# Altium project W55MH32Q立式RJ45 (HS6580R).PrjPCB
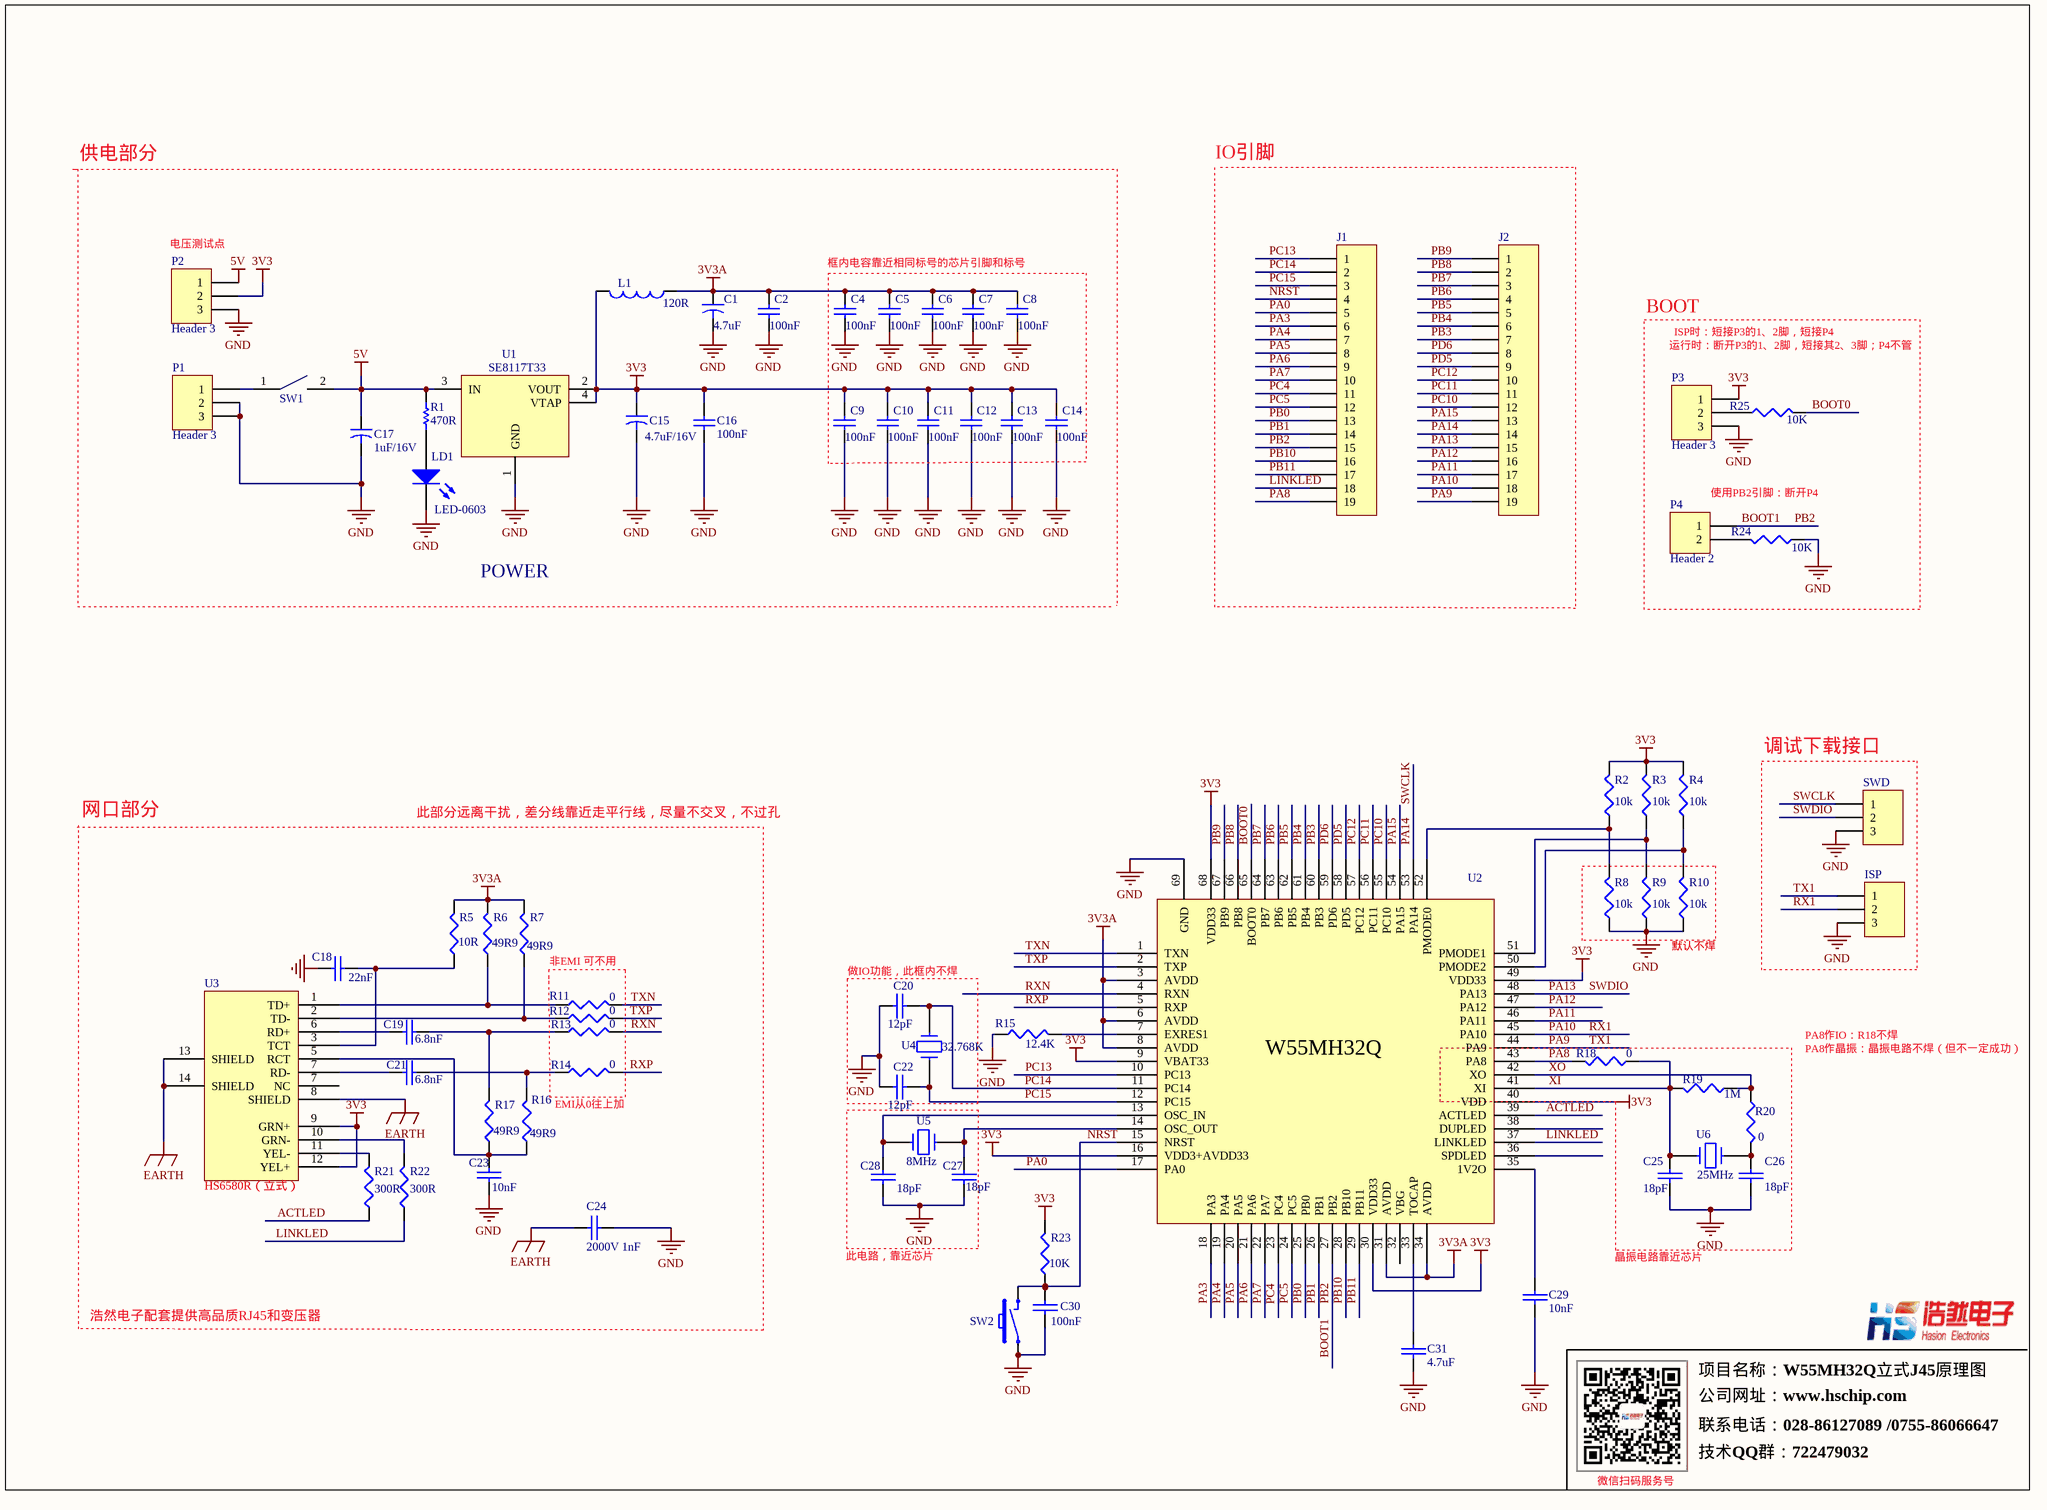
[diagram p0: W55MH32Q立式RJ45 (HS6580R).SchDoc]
1 sheet, 73 parts. Net scope: global (net labels, ports and power ports of the same name join across sheets).

## Sheet W55MH32Q立式RJ45 (HS6580R).SchDoc
size 381 x 279 mm; PageSetup: Record=PageOptions?CenterHorizontal=True?CenterVertical=True?PrintScale=0.74?XCorrection=1.00?YCorrection=1.00?PrintKind=0?BorderSize=5000000?LeftOffset=0?BottomOffset=0?Orientation=2?PaperLength=1000?PaperWidth=1000?Scale=100?PaperSource=7?PrintQuality=-4?MediaType=1?DitherType=10?PaperKind=A4?PrintScaleMode=1

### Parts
C1  4.7uF  [3216]
C2  100nF  [0402]
C4  100nF  [0402]
C5  100nF  [0402]
C6  100nF  [0402]
C7  100nF  [0402]
C8  100nF  [0402]
C9  100nF  [0402]
C10  100nF  [0402]
C11  100nF  [0402]
C12  100nF  [0402]
C13  100nF  [0402]
C14  100nF  [0402]
C15  4.7uF/16V  [3216]
C16  100nF  [0402]
C17  1uF/16V  [3216]
C18  22nF  [0402]
C19  6.8nF  [0402]
C20  12pF  [0402]
C21  6.8nF  [0402]
C22  12pF  [0402]
C23  10nF  [0402]
C24  2000V 1nF  [1808-C-SMD]
C25  18pF  [0402]
C26  18pF  [0402]
C27  18pF  [0402]
C28  18pF  [0402]
C29  10nF  [0402]
C30  100nF  [0402]
C31  4.7uF  [3216]
ISP  Header 3  [HDR1X3]  (value not drawn)
J1  Header 19  [SIP19]  (value not drawn)
J2  Header 19  [SIP19]  (value not drawn)
L1  120R  [0603]
LD1  LED-0603  [0603 - LED]
P1  Header 3  [PLUG]
P2  Header 3  [HDR1X3]
P3  Header 3  [HDR1X3]
P4  Header 2  [HDR1X2]
R1  470R  [0402]
R2  10k  [0402]
R3  10k  [0402]
R4  10k  [0402]
R5  10R  [0402]
R6  49R9  [0402]
R7  49R9  [0402]
R8  10k  [0402]
R9  10k  [0402]
R10  10k  [0402]
R11  0  [0402]
R12  0  [0402]
R13  0  [0402]
R14  0  [0402]
R15  12.4K  [0402]
R16  49R9  [0402]
R17  49R9  [0402]
R18  0  [0402]
R19  1M  [0402]
R20  0  [0402]
R21  300R  [0402]
R22  300R  [0402]
R23  10K  [0402]
R24  10K  [0402]
R25  10K  [0402]
SW1  SW  [SWITCH-3]  (value not drawn)
SW2  RSTn  [PB-4]  (value not drawn)
SWD  Header 3  [HDR1X3]  (value not drawn)
U1  SE8117T33  [SOT-223]
U2  W55MH32Q  [QFN68-W55MH32Q 8X8-P0.4-EP5.5]  (value not drawn)
U3  HS6580R（立式）  [RJ45-HS6580R]
U4  32.768K  [OSC-CH206-RA - 2]
U5  8MHz  [XTAL-49S]
U6  25MHz  [XTAL-49S]

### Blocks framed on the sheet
框内电容靠近相同标号的芯片引脚和标号: C4-C14
BOOT: P3 P4 R24 R25
调试下载接口: ISP SWD
网口部分: C18 C19 C21 C23 C24 R5-R7 R11-R14 R16 R17 R21 R22 U3
做IO功能，此框内不焊: C20 C22 U4

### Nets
3V3: C9.2 C10.2 C11.2 C12.2 C13.2 C14.2 C15.1 C16.2 L1.2 P2.2 P3.1 R2.2 R3.2 R4.2 R23.2 U1.2(VOUT) U1.4(VTAP) U2.9(VBAT33) U2.16(VDD3+AVDD33) U2.30(VDD33) U2.40(VDD) U2.49(VDD33) U2.68(VDD33) U3.9(GRN+) U3.12(YEL+)
3V3A: C1.1 C2.2 C4.2 C5.2 C6.2 C7.2 C8.2 L1.1 R5.2 R6.2 R7.2 U2.3(AVDD) U2.6(AVDD) U2.8(AVDD) U2.31(AVDD) U2.34(AVDD)
5V: C17.1 P2.1 R1.1 SW1.2 U1.3(IN)
EARTH: C24.1 U3.8(SHIELD) U3.13(SHIELD) U3.14(SHIELD)
GND: C1.2 C2.1 C4.1 C5.1 C6.1 C7.1 C8.1 C9.1 C10.1 C11.1 C12.1 C13.1 C14.1 C15.2 C16.1 C17.2 C18.1 C20.1 C22.1 C23.1 C24.2 C25.2 C26.2 C27.2 C28.2 C29.2 C30.1 C31.2 ISP.3 LD1.2(K) P1.2 P1.3 P2.3 P3.3 R8.1 R9.1 R10.1 R15.1 R24.1 SW2.1 SWD.3 U1.1(GND) U2.69(GND)
ACTLED: R21.1 U2.39(ACTLED)
BOOT0: R25.1 U2.65(BOOT0)
BOOT1: J1.15 P4.1 U2.27(PB2)  [also labelled PB2]
LINKLED: J1.18 R22.1 U2.37(LINKLED)
NRST: C30.2 J1.4 R23.1 SW2.2 U2.15(NRST)
PA0: J1.5 U2.17(PA0)
PA3: J1.6 U2.18(PA3)
PA4: J1.7 U2.19(PA4)
PA5: J1.8 U2.20(PA5)
PA6: J1.9 U2.21(PA6)
PA7: J1.10 U2.22(PA7)
PA8: J1.19 R18.2 U2.43(PA8)
PA9: ISP.1 J2.19 U2.44(PA9)  [also labelled TX1]
PA10: ISP.2 J2.18 U2.45(PA10)  [also labelled RX1]
PA11: J2.17 U2.46(PA11)
PA12: J2.16 U2.47(PA12)
PA13: J2.15 SWD.2 U2.48(PA13)  [also labelled SWDIO]
PA14: J2.14 SWD.1 U2.53(PA14)  [also labelled SWCLK]
PA15: J2.13 U2.54(PA15)
PB0: J1.13 U2.25(PB0)
PB1: J1.14 U2.26(PB1)
PB3: J2.7 U2.60(PB3)
PB4: J2.6 U2.61(PB4)
PB5: J2.5 U2.62(PB5)
PB6: J2.4 U2.63(PB6)
PB7: J2.3 U2.64(PB7)
PB8: J2.2 U2.66(PB8)
PB9: J2.1 U2.67(PB9)
PB10: J1.16 U2.28(PB10)
PB11: J1.17 U2.29(PB11)
PC4: J1.11 U2.23(PC4)
PC5: J1.12 U2.24(PC5)
PC10: J2.12 U2.55(PC10)
PC11: J2.11 U2.56(PC11)
PC12: J2.10 U2.57(PC12)
PC13: J1.1 U2.10(PC13)
PC14: C20.2 J1.2 U2.11(PC14) U4.1
PC15: C22.2 J1.3 U2.12(PC15) U4.2
PD5: J2.9 U2.58(PD5)
PD6: J2.8 U2.59(PD6)
RXN: R13.2 U2.4(RXN)
RXP: R14.2 U2.5(RXP)
TXN: R11.2 U2.1(TXN)
TXP: R12.2 U2.2(TXP)
XI: C25.1 R18.1 R19.2 U2.41(XI) U6.1
XO: R19.1 R20.1 U2.42(XO)
NetC18_2: C18.2 R5.1 U3.3(TCT)
NetC19_1: C19.1 U3.6(RD+)
NetC19_2: C19.2 R13.1 R17.2
NetC21_1: C21.1 U3.7(RD-)
NetC21_2: C21.2 R14.1 R16.2
NetC23_2: C23.2 R16.1 R17.1 U3.5(RCT)
NetC26_1: C26.1 R20.2 U6.2
NetC27_1: C27.1 U2.14(OSC_OUT) U5.1
NetC28_1: C28.1 U2.13(OSC_IN) U5.2
NetC29_1: C29.1 U2.35(1V2O)
NetC31_1: C31.1 U2.33(TOCAP)
NetLD1_1: LD1.1(A) R1.2
NetP1_1: P1.1 SW1.1
NetP3_2: P3.2 R25.2
NetP4_2: P4.2 R24.2
NetR2_1: R2.1 R8.2 U2.52(PMODE0)
NetR3_1: R3.1 R9.2 U2.51(PMODE1)
NetR4_1: R4.1 R10.2 U2.50(PMODE2)
NetR6_1: R6.1 R11.1 U3.1(TD+)
NetR7_1: R7.1 R12.1 U3.2(TD-)
NetR15_2: R15.2 U2.7(EXRES1)
NetR21_2: R21.2 U3.11(YEL-)
NetR22_2: R22.2 U3.10(GRN-)

Not connected (* = marked no-connect by the designer): U2 32(VBG) 36(SPDLED) 38(DUPLED)

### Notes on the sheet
- 供电部分
- IO引脚
- (near P2) 电压测试点
- 运行时：断开P3的1、2脚，短接其2、3脚；P4不管
- ISP时：短接P3的1、2脚，短接P4
- 使用PB2引脚：断开P4
- POWER
- 此部分远离干扰，差分线靠近走平行线，尽量不交叉，不过孔
- 非EMI 可不用
- 默认不焊
- PA8作IO：R18不焊
- EMI从0往上加
- PA8作晶振：晶振电路不焊（但不一定成功）
- 此电路，靠近芯片
- 晶振电路靠近芯片
- 浩然电子配套提供高品质RJ45和变压器
- 项目名称：W55MH32Q立式J45原理图
- 公司网址：www.hschip.com
- 联系电话：028-86127089 /0755-86066647
- 微信扫码服务号
- 技术QQ群：722479032

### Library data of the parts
C1 C15 C17 = CAP-A Size: Tantla CAP A Size EIA/IECQ 3216
C2 C4-C14 C16 = CAP-0603: Ceramic CAP 0603(1608)
C18-C31 = CAP: Capacitor
ISP P1-P3 SWD = Header 3: Header, 3-Pin
J1 J2 = Header 19: Header, 18-Pin
L1 = IND-0603: Inductor 0603(1608)
P4 = Header 2: Header, 2-Pin
R1 = RES-0603
R2-R14 R16-R25 = Res3: Resistor
R15 = RES1
SW1 = swtch
SW2 = IT-1101NHA-180G: TACT Switch (SMD)
U1 = AME8815BEGT330Z: 1.5A CMOS LDO
U2 = W55MH32_68QFN_EVB
U3 = HS6580R
U4-U6 = CRYSTAL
